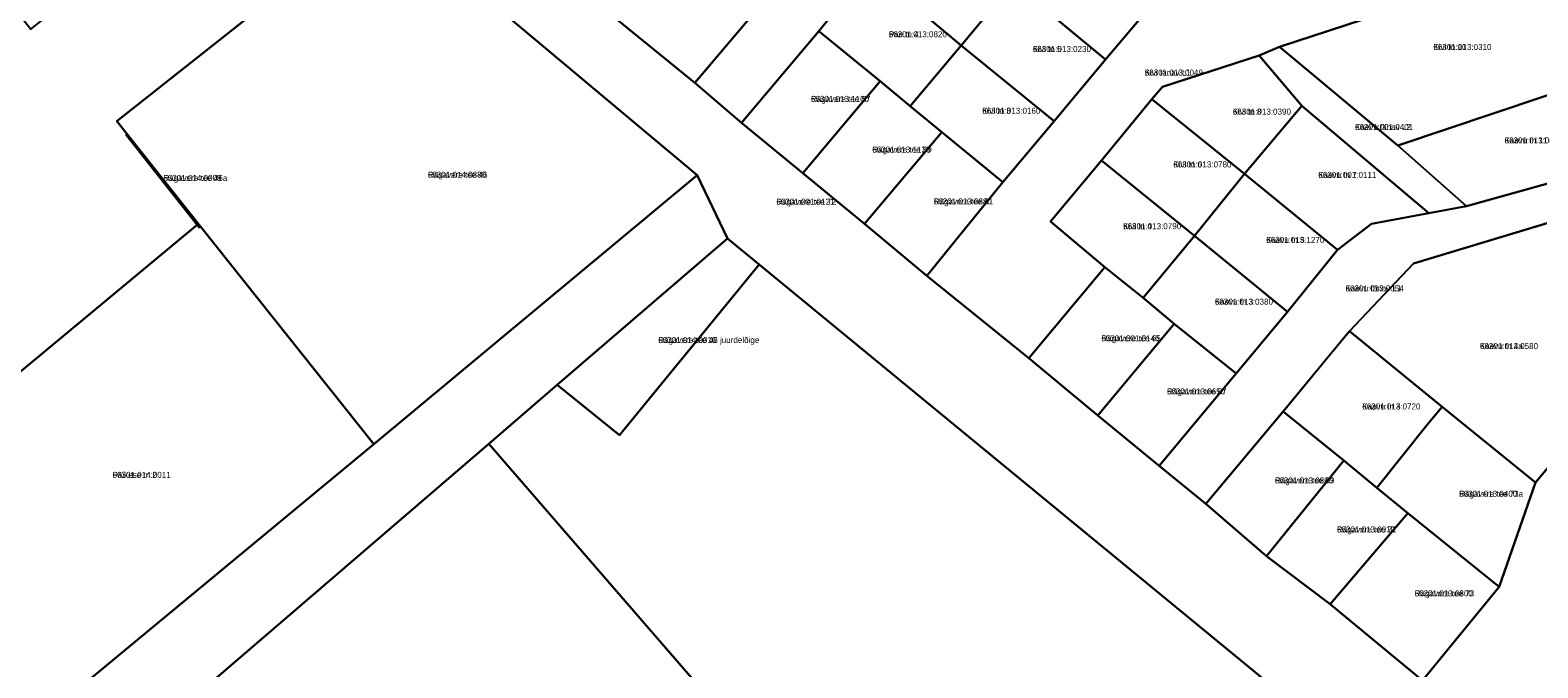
# Model space of a CAD drawing. Extents: x 632278 to 636344, y 6578401 to 6583362.
# Drawn here: x 635426 to 635802.2, y 6580206 to 6580365.1 of the extents above; entities that cross this region are included whole.
import ezdxf

# ---------------------------------------------------------------- set-up
doc = ezdxf.new("R2010")
doc.units = 0
for name, color, linetype in [('L_AADRESS', 7, 'Continuous'), ('PIIR', 7, 'Continuous'), ('TUNNUS', 7, 'Continuous')]:
    doc.layers.add(name, color=color, linetype=linetype)

msp = doc.modelspace()

# ---------------------------------------------------------------- linework, layer by layer
at = {"layer": 'PIIR'}
for points in [[(635591.82, 6580351.91), (635608.04, 6580371.06), (635623.68, 6580389.87), (635636.52, 6580405.39), (635655.62, 6580428.51), (635667.08, 6580442.68), (635686.71, 6580466.19), (635707.04, 6580490.82), (635708.89, 6580493.06), (635714.06, 6580498.56), (635756.47, 6580515.62), (635764.72, 6580502.67), (635741.92, 6580493.69), (635722.58, 6580485.64), (635699.1, 6580457.17), (635679.06, 6580432.87), (635667.18, 6580418.97), (635648.14, 6580395.77), (635635.42, 6580380.52), (635622.77, 6580364.81), (635603.53, 6580341.98)], [(635489.11, 6580415.36), (635513.87, 6580394.76), (635447.63, 6580342.41), (635450.21, 6580339.12), (635449.99, 6580338.94), (635467.67, 6580316.49), (635381.07, 6580244.67), (635374.64, 6580252.56), (635336.61, 6580299.27), (635317.1, 6580323.16), (635351.3, 6580351.27), (635393.37, 6580386.15), (635403.27, 6580394.42), (635426.14, 6580365.34), (635476.07, 6580404.98)], [(635694.32, 6580357.75), (635671.28, 6580376.92), (635689.95, 6580399.99), (635713.75, 6580380.81)], [(635447.63, 6580342.41), (635513.87, 6580394.76), (635592.45, 6580328.94), (635511.73, 6580261.79), (635468.5, 6580316.13)], [(635648.14, 6580395.77), (635671.28, 6580376.92), (635658.3, 6580361.28), (635635.42, 6580380.52)], [(635608.04, 6580371.06), (635591.82, 6580351.91), (635568.74, 6580370.72), (635585.37, 6580389.85)], [(635737.74, 6580360.91), (635808.04, 6580383.95), (635813.96, 6580358.43), (635815.34, 6580352.49), (635767.28, 6580336.34)], [(635622.77, 6580364.81), (635635.42, 6580380.52), (635658.3, 6580361.28), (635645.54, 6580346.14), (635638.12, 6580352.4)], [(635671.28, 6580376.92), (635694.32, 6580357.75), (635681.51, 6580342.36), (635658.3, 6580361.28)], [(635603.53, 6580341.98), (635622.77, 6580364.81), (635638.12, 6580352.4), (635618.76, 6580329.45)], [(635681.51, 6580342.36), (635668.71, 6580327.17), (635653.49, 6580339.64), (635645.54, 6580346.14), (635658.3, 6580361.28)], [(635743.32, 6580346.18), (635728.97, 6580329.24), (635705.9, 6580347.87), (635708.51, 6580350.92), (635732.67, 6580358.81)], [(635732.67, 6580358.81), (635737.74, 6580360.91), (635767.28, 6580336.34), (635784.4, 6580321.17), (635775.02, 6580319.42), (635743.32, 6580346.18)], [(635618.76, 6580329.45), (635638.12, 6580352.4), (635645.54, 6580346.14), (635653.49, 6580339.64), (635634.2, 6580316.79)], [(635707.7, 6580256.38), (635726.89, 6580279.39), (635739.68, 6580294.78), (635752.22, 6580310.27), (635760.7, 6580316.73), (635775.02, 6580319.42), (635784.4, 6580321.17), (635820.5, 6580331.24), (635842.27, 6580338.08), (635863.27, 6580343.03), (635895.15, 6580351.15), (635900.69, 6580352.93), (635904.87, 6580343.85), (635894.61, 6580340.56), (635854.04, 6580329.83), (635810.79, 6580318.83), (635771.17, 6580306.9), (635755.18, 6580289.97), (635738.6, 6580269.95), (635719.38, 6580246.9)], [(635819.97, 6580332.88), (635820.5, 6580331.24), (635784.4, 6580321.17), (635767.28, 6580336.34), (635815.34, 6580352.49)], [(635705.9, 6580347.87), (635728.97, 6580329.24), (635716.53, 6580313.8), (635693.33, 6580332.57)], [(635728.97, 6580329.24), (635743.32, 6580346.18), (635775.02, 6580319.42), (635760.7, 6580316.73), (635752.22, 6580310.27)], [(635450.21, 6580339.12), (635468.5, 6580316.13), (635468.17, 6580315.87), (635467.67, 6580316.49), (635449.99, 6580338.94)], [(635634.2, 6580316.79), (635653.49, 6580339.64), (635668.71, 6580327.17), (635649.69, 6580303.82)], [(635680.62, 6580317.33), (635693.33, 6580332.57), (635716.53, 6580313.8), (635703.67, 6580298.29), (635694.14, 6580305.99)], [(635284.72, 6580049.77), (635376.26, 6580126.16), (635370.52, 6580133.19), (635364.8, 6580140.19), (635383.48, 6580155.49), (635425.33, 6580190.26), (635511.73, 6580261.79), (635592.45, 6580328.94), (635600.03, 6580313.12), (635557.53, 6580276.59), (635540.41, 6580261.9), (635432.99, 6580169.56), (635440.4, 6580160.92), (635420.43, 6580144.16), (635306.27, 6580046), (635295.31, 6580036.98)], [(635728.97, 6580329.24), (635752.22, 6580310.27), (635739.68, 6580294.78), (635716.53, 6580313.8)], [(635755.18, 6580289.97), (635771.17, 6580306.9), (635810.79, 6580318.83), (635816.65, 6580270.2), (635801.61, 6580252.19), (635778.32, 6580271.13)], [(635467.67, 6580316.49), (635468.17, 6580315.87), (635468.5, 6580316.13), (635511.73, 6580261.79), (635425.33, 6580190.26), (635381.07, 6580244.67)], [(635703.67, 6580298.29), (635716.53, 6580313.8), (635739.68, 6580294.78), (635726.89, 6580279.39), (635711.42, 6580291.83)], [(635600.03, 6580313.12), (635607.93, 6580306.59), (635573.07, 6580264.02), (635557.53, 6580276.59)], [(635540.41, 6580261.9), (635557.53, 6580276.59), (635573.07, 6580264.02), (635607.93, 6580306.59), (635748.53, 6580191), (635716.5, 6580147.27), (635687.33, 6580107.85), (635681.84, 6580103.36), (635679.61, 6580101.33), (635613.33, 6580177.77)], [(635675.14, 6580283.28), (635694.14, 6580305.99), (635703.67, 6580298.29), (635711.42, 6580291.83), (635692.42, 6580268.95), (635684.6, 6580275.4)], [(635692.42, 6580268.95), (635711.42, 6580291.83), (635726.89, 6580279.39), (635707.7, 6580256.38)], [(635738.6, 6580269.95), (635751.4, 6580285.43), (635755.18, 6580289.97), (635778.32, 6580271.13), (635774.51, 6580266.52), (635761.98, 6580250.91), (635753.77, 6580257.71)], [(635719.38, 6580246.9), (635738.6, 6580269.95), (635753.77, 6580257.71), (635734.44, 6580233.83)], [(635792.57, 6580226.19), (635769.7, 6580244.57), (635761.98, 6580250.91), (635774.51, 6580266.52), (635778.32, 6580271.13), (635801.61, 6580252.19)], [(635792.57, 6580226.19), (635801.61, 6580252.19), (635816.65, 6580270.2), (635820.91, 6580232.27), (635812.68, 6580231.45), (635815.07, 6580206.46), (635858.31, 6580209.88), (635910.07, 6580213.66), (635917.38, 6580200.91), (635926.89, 6580181.62), (635938.11, 6580161.38), (635945.86, 6580145.59), (635963.17, 6580113.04), (635977.93, 6580085.79), (635990.28, 6580061.61), (635974.57, 6580071.64), (635909.08, 6580111.48), (635932.52, 6580145.26), (635902.43, 6580203.63), (635865.45, 6580199.21), (635789.06, 6580189.11), (635773.41, 6580202.85)], [(635432.99, 6580169.56), (635540.41, 6580261.9), (635613.33, 6580177.77), (635553.81, 6580127.39), (635533.46, 6580110.4), (635509.2, 6580138.23), (635499.34, 6580129.9), (635489.75, 6580121.83), (635480.55, 6580114.08), (635440.4, 6580160.92)], [(635734.44, 6580233.83), (635753.77, 6580257.71), (635761.98, 6580250.91), (635769.7, 6580244.57), (635750.34, 6580221.86)], [(635769.7, 6580244.57), (635792.57, 6580226.19), (635773.41, 6580202.85), (635750.34, 6580221.86)]]:
    msp.add_lwpolyline(points, close=True, dxfattribs=at)
for points in [[(635413.91, 6580497.17), (635454.49, 6580462.68), (635469.81, 6580449.57), (635487.73, 6580437.31), (635511.19, 6580418.34), (635533.94, 6580399.4), (635545.81, 6580389.88), (635568.74, 6580370.72), (635591.82, 6580351.91), (635603.53, 6580341.98), (635618.76, 6580329.45), (635634.2, 6580316.79), (635649.69, 6580303.82), (635675.14, 6580283.28), (635684.6, 6580275.4), (635692.42, 6580268.95), (635707.7, 6580256.38), (635719.38, 6580246.9), (635734.44, 6580233.83), (635750.34, 6580221.86), (635773.41, 6580202.85)], [(635748.53, 6580191), (635607.93, 6580306.59), (635600.03, 6580313.12), (635592.45, 6580328.94), (635513.87, 6580394.76), (635489.11, 6580415.36), (635476.63, 6580425.76), (635459.02, 6580440.91), (635451.83, 6580446.86), (635421.25, 6580472.2)], [(635808.04, 6580383.95), (635737.74, 6580360.91), (635732.67, 6580358.81), (635708.51, 6580350.92), (635705.9, 6580347.87), (635693.33, 6580332.57), (635680.62, 6580317.33), (635694.14, 6580305.99), (635675.14, 6580283.28), (635649.69, 6580303.82), (635668.71, 6580327.17), (635681.51, 6580342.36), (635694.32, 6580357.75), (635713.75, 6580380.81), (635740.39, 6580382.76), (635759.94, 6580388.42), (635780.95, 6580394.74), (635805.21, 6580403.87)]]:
    msp.add_lwpolyline(points, dxfattribs=at)

# ---------------------------------------------------------------- texts
at = {"layer": 'L_AADRESS'}
for s, p in [('Pae tn 4', (635640.23, 6580363.33)), ('Kivi tn 5', (635676.18, 6580359.64)), ('Kivi tn 10', (635776.11, 6580360.15)), ('Kivi tänav L1', (635704.11, 6580353.77)), ('Rägavere tee 57', (635620.82, 6580347.2)), ('Kivi tn 3', (635663.55, 6580344.23)), ('Kivi tn 8', (635726.08, 6580344.02)), ('Kaevu tänav L2', (635756.56, 6580340.17)), ('Rägavere tee 59', (635636.12, 6580334.55)), ('Kaevu tn 11', (635793.89, 6580336.83)), ('Kivi tn 6', (635711.23, 6580330.84)), ('Rägavere tee 46a', (635459.25, 6580327.48)), ('Rägavere tee 46', (635525.25, 6580328.28)), ('Kaevu tn 7', (635747.4, 6580328.23)), ('Rägavere tee T2', (635612.19, 6580321.55)), ('Rägavere tee 61', (635651.46, 6580321.61)), ('Kivi tn 4', (635698.7, 6580315.43)), ('Kaevu tn 5', (635734.4, 6580312.01)), ('Kaevu tänav L1', (635754.2, 6580299.91)), ('Kaevu tn 3', (635721.59, 6580296.6)), ('Rägavere tee 48 juurdelõige', (635582.73, 6580287.03)), ('Rägavere tee 65', (635693.28, 6580287.47)), ('Kaevu tn 4a', (635787.73, 6580285.51)), ('Rägavere tee 67', (635709.66, 6580274.21)), ('Kaevu tn 4', (635758.38, 6580270.44)), ('Päikese tn 2', (635446.57, 6580253.38)), ('Rägavere tee 69', (635736.58, 6580251.99)), ('Rägavere tee 73a', (635782.55, 6580248.66)), ('Rägavere tee 71', (635752.07, 6580239.75)), ('Rägavere tee 73', (635771.46, 6580223.81))]:
    msp.add_text(s, height=1.5, dxfattribs=at).set_placement(p)
at = {"layer": 'TUNNUS'}
for s, p in [('66301:013:0820', (635640.23, 6580363.33)), ('66301:013:0230', (635676.18, 6580359.64)), ('66301:013:0310', (635776.11, 6580360.15)), ('66301:013:0049', (635704.11, 6580353.77)), ('66301:013:1100', (635620.82, 6580347.2)), ('66301:013:0160', (635663.55, 6580344.23)), ('66301:013:0390', (635726.08, 6580344.02)), ('66301:001:0401', (635756.56, 6580340.17)), ('66301:013:1120', (635636.12, 6580334.55)), ('66301:013:0090', (635793.89, 6580336.83)), ('66301:013:0780', (635711.23, 6580330.84)), ('66301:014:0009', (635459.25, 6580327.48)), ('66301:014:0880', (635525.25, 6580328.28)), ('66301:001:0111', (635747.4, 6580328.23)), ('66301:001:0121', (635612.19, 6580321.55)), ('66301:013:0880', (635651.46, 6580321.61)), ('66301:013:0790', (635698.7, 6580315.43)), ('66301:013:1270', (635734.4, 6580312.01)), ('66301:013:0054', (635754.2, 6580299.91)), ('66301:013:0380', (635721.59, 6580296.6)), ('66301:014:0016', (635582.73, 6580287.03)), ('66301:001:0146', (635693.28, 6580287.47)), ('66301:013:0580', (635787.73, 6580285.51)), ('66301:013:0650', (635709.66, 6580274.21)), ('66301:013:0720', (635758.38, 6580270.44)), ('66301:014:0011', (635446.57, 6580253.38)), ('66301:013:0860', (635736.58, 6580251.99)), ('66301:013:0400', (635782.55, 6580248.66)), ('66301:013:0910', (635752.07, 6580239.75)), ('66301:013:0800', (635771.46, 6580223.81))]:
    msp.add_text(s, height=1.5, dxfattribs=at).set_placement(p)

doc.saveas('drawing.dxf')
